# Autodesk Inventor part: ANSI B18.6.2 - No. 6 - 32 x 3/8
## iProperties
Author: Elise Moss
Created: 2002-03
Part Number: ANSI B18.6.2 - No. 6 - 32 x 3/8
Catalog Web Link: file:///C:/Program%20Files/Autodesk/Inventor%205/Content/Ansi/index.htm?doNavigateId=BB769556-4EDA-4C0C-A29A-0242926003DE|4ADB4B3CD7EB11D4BA8200C04F798F98|true
Description: Slotted Flat Countersunk Head Cap Screw
Document SubType Name: Standard Catalog Part
Standard: ANSI B18.6.2 - No. 6 - 32 x 3/8
Designer: Elise Moss
CLASSIFICATION: 31161513 un/spsc
MANUFACTURER: ANSI Standard System
Control State: 0
Master: False
Checked Out: False
PropertySet Name: Design Tracking Control
Shininess: 64.0
Angle Display Precision: 2
Document Length Units: 11269
Document Angle Units: 11283
Document Time Units: 11279
Document Mass Units: 11290
Document Length Units Precision: 3
Document Angle Units Precision: 2
Compacted: True
PropertySet Name: _Private Model Information
Density: 0.0
Volumn: 0.0
Area: 0.0
PropertySet Name: Model Information
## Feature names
1. Base1
